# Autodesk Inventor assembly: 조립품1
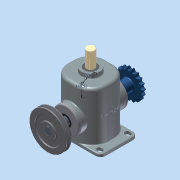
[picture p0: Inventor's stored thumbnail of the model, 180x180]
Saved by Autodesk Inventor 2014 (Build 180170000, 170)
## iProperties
Created: 2014-12
Part Number: 조립품1
Document SubType Name: Assembly
Designer: user
Author: user
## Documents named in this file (15)
- C:\Users\user\Desktop\341208V1036\조립품1.iam
- C:\Users\user\Desktop\341208V1036\본체.ipt
- C:\Users\user\Desktop\341208V1036\편심축.ipt
- C:\Users\user\Desktop\341208V1036\멈춤링.ipt
- C:\Users\user\Desktop\341208V1036\베어링 6205.ipt
- C:\Users\user\Desktop\341208V1036\커버.ipt
- C:\Users\user\Desktop\341208V1036\오일실.ipt
- C:\Users\user\Desktop\341208V1036\키 8x8.ipt
- C:\Users\user\Desktop\341208V1036\V-벨트풀리.ipt
- C:\Users\user\Desktop\341208V1036\체인 스프로킷.ipt
- C:\Users\user\Desktop\341208V1036\멈춤나사 M5x0.5.ipt
- C:\Users\user\Desktop\341208V1036\부시.ipt
- C:\Users\user\Desktop\341208V1036\슬라이드.ipt
- C:\Users\user\Desktop\341208V1036\스프링.ipt
- C:\Users\user\Desktop\341208V1036\M4x0.5.ipt
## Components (8 placed, 3 different names)
1. V-벨트풀리:1 — 각도:1, 각도:3
2. 5-체인 스프로킷:1 — 각도:2
3. M4x0.5:1 — 각도:6
4. M4x0.5:2 — 각도:4
5. M4x0.5:3 — 각도:5
6. M4x0.5:4 — 각도:8
7. M4x0.5:5 — 각도:9
8. M4x0.5:6 — 각도:7
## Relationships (9: Angle 9)
- 각도:1 [Angle]: V-벨트풀리:1
- 각도:2 [Angle]: 5-체인 스프로킷:1
- 각도:3 [Angle]: V-벨트풀리:1
- 각도:4 [Angle]: M4x0.5:2
- 각도:5 [Angle]: M4x0.5:3
- 각도:6 [Angle]: M4x0.5:1
- 각도:7 [Angle]: M4x0.5:6
- 각도:8 [Angle]: M4x0.5:4
- 각도:9 [Angle]: M4x0.5:5
